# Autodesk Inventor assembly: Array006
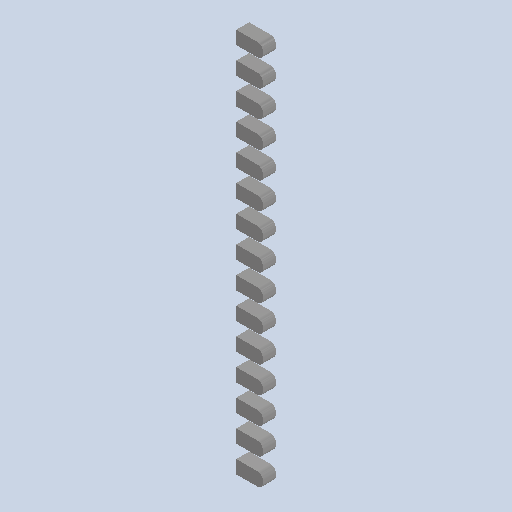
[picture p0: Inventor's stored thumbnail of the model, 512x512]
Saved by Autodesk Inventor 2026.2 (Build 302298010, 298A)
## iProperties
Created: 2026-10
Part Number: Array006
Document SubType Name: Assembly
Designer: mel
Author: mel
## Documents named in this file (16)
- D:\travail\année 2026-2027\1 sti2d IT\poubelle à verre\raspberry-pico-2-microcontroller-rp2350-1.snapshot.5\raspberry_pico_2\raspberry_pico_2\Array006.iam
- D:\travail\année 2026-2027\1 sti2d IT\poubelle à verre\raspberry-pico-2-microcontroller-rp2350-1.snapshot.5\raspberry_pico_2\raspberry_pico_2\Fillet030.ipt
- D:\travail\année 2026-2027\1 sti2d IT\poubelle à verre\raspberry-pico-2-microcontroller-rp2350-1.snapshot.5\raspberry_pico_2\raspberry_pico_2\Fillet031.ipt
- D:\travail\année 2026-2027\1 sti2d IT\poubelle à verre\raspberry-pico-2-microcontroller-rp2350-1.snapshot.5\raspberry_pico_2\raspberry_pico_2\Fillet032.ipt
- D:\travail\année 2026-2027\1 sti2d IT\poubelle à verre\raspberry-pico-2-microcontroller-rp2350-1.snapshot.5\raspberry_pico_2\raspberry_pico_2\Fillet033.ipt
- D:\travail\année 2026-2027\1 sti2d IT\poubelle à verre\raspberry-pico-2-microcontroller-rp2350-1.snapshot.5\raspberry_pico_2\raspberry_pico_2\Fillet034.ipt
- D:\travail\année 2026-2027\1 sti2d IT\poubelle à verre\raspberry-pico-2-microcontroller-rp2350-1.snapshot.5\raspberry_pico_2\raspberry_pico_2\Fillet035.ipt
- D:\travail\année 2026-2027\1 sti2d IT\poubelle à verre\raspberry-pico-2-microcontroller-rp2350-1.snapshot.5\raspberry_pico_2\raspberry_pico_2\Fillet036.ipt
- D:\travail\année 2026-2027\1 sti2d IT\poubelle à verre\raspberry-pico-2-microcontroller-rp2350-1.snapshot.5\raspberry_pico_2\raspberry_pico_2\Fillet037.ipt
- D:\travail\année 2026-2027\1 sti2d IT\poubelle à verre\raspberry-pico-2-microcontroller-rp2350-1.snapshot.5\raspberry_pico_2\raspberry_pico_2\Fillet038.ipt
- D:\travail\année 2026-2027\1 sti2d IT\poubelle à verre\raspberry-pico-2-microcontroller-rp2350-1.snapshot.5\raspberry_pico_2\raspberry_pico_2\Fillet039.ipt
- D:\travail\année 2026-2027\1 sti2d IT\poubelle à verre\raspberry-pico-2-microcontroller-rp2350-1.snapshot.5\raspberry_pico_2\raspberry_pico_2\Fillet040.ipt
- D:\travail\année 2026-2027\1 sti2d IT\poubelle à verre\raspberry-pico-2-microcontroller-rp2350-1.snapshot.5\raspberry_pico_2\raspberry_pico_2\Fillet041.ipt
- D:\travail\année 2026-2027\1 sti2d IT\poubelle à verre\raspberry-pico-2-microcontroller-rp2350-1.snapshot.5\raspberry_pico_2\raspberry_pico_2\Fillet042.ipt
- D:\travail\année 2026-2027\1 sti2d IT\poubelle à verre\raspberry-pico-2-microcontroller-rp2350-1.snapshot.5\raspberry_pico_2\raspberry_pico_2\Fillet043.ipt
- D:\travail\année 2026-2027\1 sti2d IT\poubelle à verre\raspberry-pico-2-microcontroller-rp2350-1.snapshot.5\raspberry_pico_2\raspberry_pico_2\Fillet044.ipt
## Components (15 placed, 15 different names)
1. 2722
2. 2723
3. 2724
4. 2725
5. 2726
6. 2727
7. 2728
8. 2729
9. 2730
10. 2731
11. 2732
12. 2733
13. 2734
14. 2735
15. 2736
